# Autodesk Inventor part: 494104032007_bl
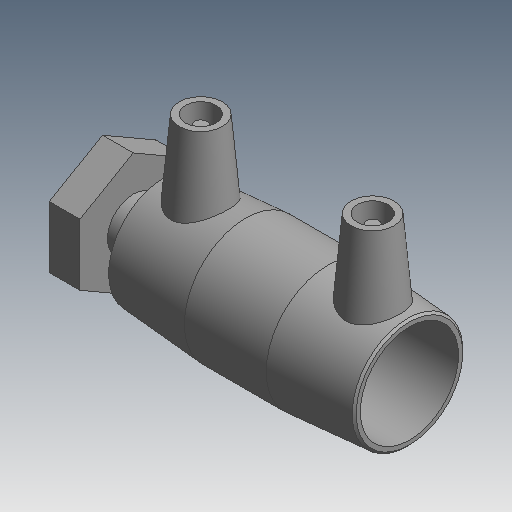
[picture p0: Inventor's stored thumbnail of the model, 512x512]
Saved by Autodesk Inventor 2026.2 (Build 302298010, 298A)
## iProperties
Created: 2017-06
Part Number: 494104032007_bl
Material: Generic
Description: PLASSON FEMALE FREE NUT TRANSITION COUPLER 32-3/4"
Document SubType Name: Modeling
Designer: KIM
Mass: 55.0731 g
Surface Area: 148.067 cm^2
Volume: 55.0731 cm^3
Density: 1 g/cm^3
Appearance: Default
Author: KIM
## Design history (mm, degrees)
derived "494104.ipt"
feature "Solid1::494104.ipt" dims "ScaleForDerivedMember" = 10
tag "TaggingFeature1"
body "Solid1"
other parameters: "d1" = 32 [user parameter], "d3" = 39 [user parameter], "d4" = 26.66667 [user parameter], "d5" = 36 [user parameter], "d6" = 30.4 [user parameter], "d7" = 32 [user parameter], "d29" = 42 [user parameter], "d30" = 14 [user parameter], "d31" = 28 [user parameter], "d34" = 5 deg [user parameter], "d41" = 4 [user parameter], "d42" = 14 [user parameter], "d43" = 0 [user parameter], "d48" = 3 [user parameter], "d49" = 0 [user parameter], "d80" = 0.64 [user parameter], "d84" = 6.6 [user parameter], "d85" = 0.66 [user parameter], "d86" = 19.2936 [user parameter], "d87" = 24.117 [user parameter], "d88" = 27.117 [user parameter], "d96" = 16.8819 [user parameter], "d97" = 0 [user parameter], "d98" = 2.4117 [user parameter], "d99" = 2.4117 [user parameter], "d106" = 0 [user parameter], "d107" = 6.5 [user parameter], "d_" = 32 [user parameter], "L_1" = 39 [user parameter], "A_" = 42 [user parameter], "d_2" = 12 [user parameter], "D_" = 14 [user parameter], "G_" = 24.117 [user parameter], "d102" = 27.117 [user parameter]
